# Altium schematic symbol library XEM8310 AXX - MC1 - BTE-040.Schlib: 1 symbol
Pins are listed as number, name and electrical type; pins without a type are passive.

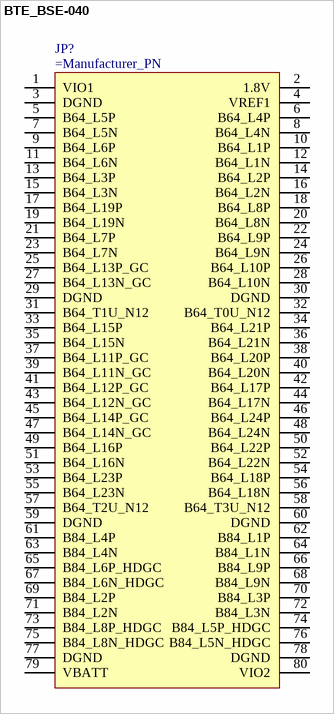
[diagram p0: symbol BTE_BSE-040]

## BTE_BSE-040
designator JP?
pins: 1 VIO1, 2 1.8V, 3 DGND, 4 VREF1, 5 B64_L5P, 6 B64_L4P, 7 B64_L5N, 8 B64_L4N, 9 B64_L6P, 10 B64_L1P, 11 B64_L6N, 12 B64_L1N, 13 B64_L3P, 14 B64_L2P, 15 B64_L3N, 16 B64_L2N, 17 B64_L19P, 18 B64_L8P, 19 B64_L19N, 20 B64_L8N, 21 B64_L7P, 22 B64_L9P, 23 B64_L7N, 24 B64_L9N, 25 B64_L13P_GC, 26 B64_L10P, 27 B64_L13N_GC, 28 B64_L10N, 29 DGND, 30 DGND, 31 B64_T1U_N12, 32 B64_T0U_N12, 33 B64_L15P, 34 B64_L21P, 35 B64_L15N, 36 B64_L21N, 37 B64_L11P_GC, 38 B64_L20P, 39 B64_L11N_GC, 40 B64_L20N, 41 B64_L12P_GC, 42 B64_L17P, 43 B64_L12N_GC, 44 B64_L17N, 45 B64_L14P_GC, 46 B64_L24P, 47 B64_L14N_GC, 48 B64_L24N, 49 B64_L16P, 50 B64_L22P, 51 B64_L16N, 52 B64_L22N, 53 B64_L23P, 54 B64_L18P, 55 B64_L23N, 56 B64_L18N, 57 B64_T2U_N12, 58 B64_T3U_N12, 59 DGND, 60 DGND, 61 B84_L4P, 62 B84_L1P, 63 B84_L4N, 64 B84_L1N, 65 B84_L6P_HDGC, 66 B84_L9P, 67 B84_L6N_HDGC, 68 B84_L9N, 69 B84_L2P, 70 B84_L3P, 71 B84_L2N, 72 B84_L3N, 73 B84_L8P_HDGC, 74 B84_L5P_HDGC, 75 B84_L8N_HDGC, 76 B84_L5N_HDGC, 77 DGND, 78 DGND, 79 VBATT, 80 VIO2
